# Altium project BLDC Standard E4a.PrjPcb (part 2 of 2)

## Sheet BLDC Standard sheet 4.SchDoc
size 431 x 279 mm; Date: Not shown in title block; ApprovedBy: Not shown in title block; CheckedBy: Not shown in title block; Author: Not shown in title block; CompanyName: Not shown in title block; Engineer: Not shown in title block; Organization: Not shown in title block; Address1: Not shown in title block; Address2: Not shown in title block; Address3: Not shown in title block; Address4: Not shown in title block; DocumentNumber: 1; Revision: Use project parameter SCH_Rev; SheetNumber: 4; SheetTotal: 4; PageSetup: Record=PageOptions|CenterHorizontal=True|CenterVertical=True|PrintScale=0.96|XCorrection=1.00|YCorrection=1.00|PrintKind=0|BorderSize=5000000|LeftOffset=0|BottomOffset=0|Orientation=2|PaperLength=1000|PaperWidth=1000|Scale=100|PaperSource=15|PrintQuality=600|MediaType=1|DitherType=10|PaperKind=11x17|PrintScaleMode=1
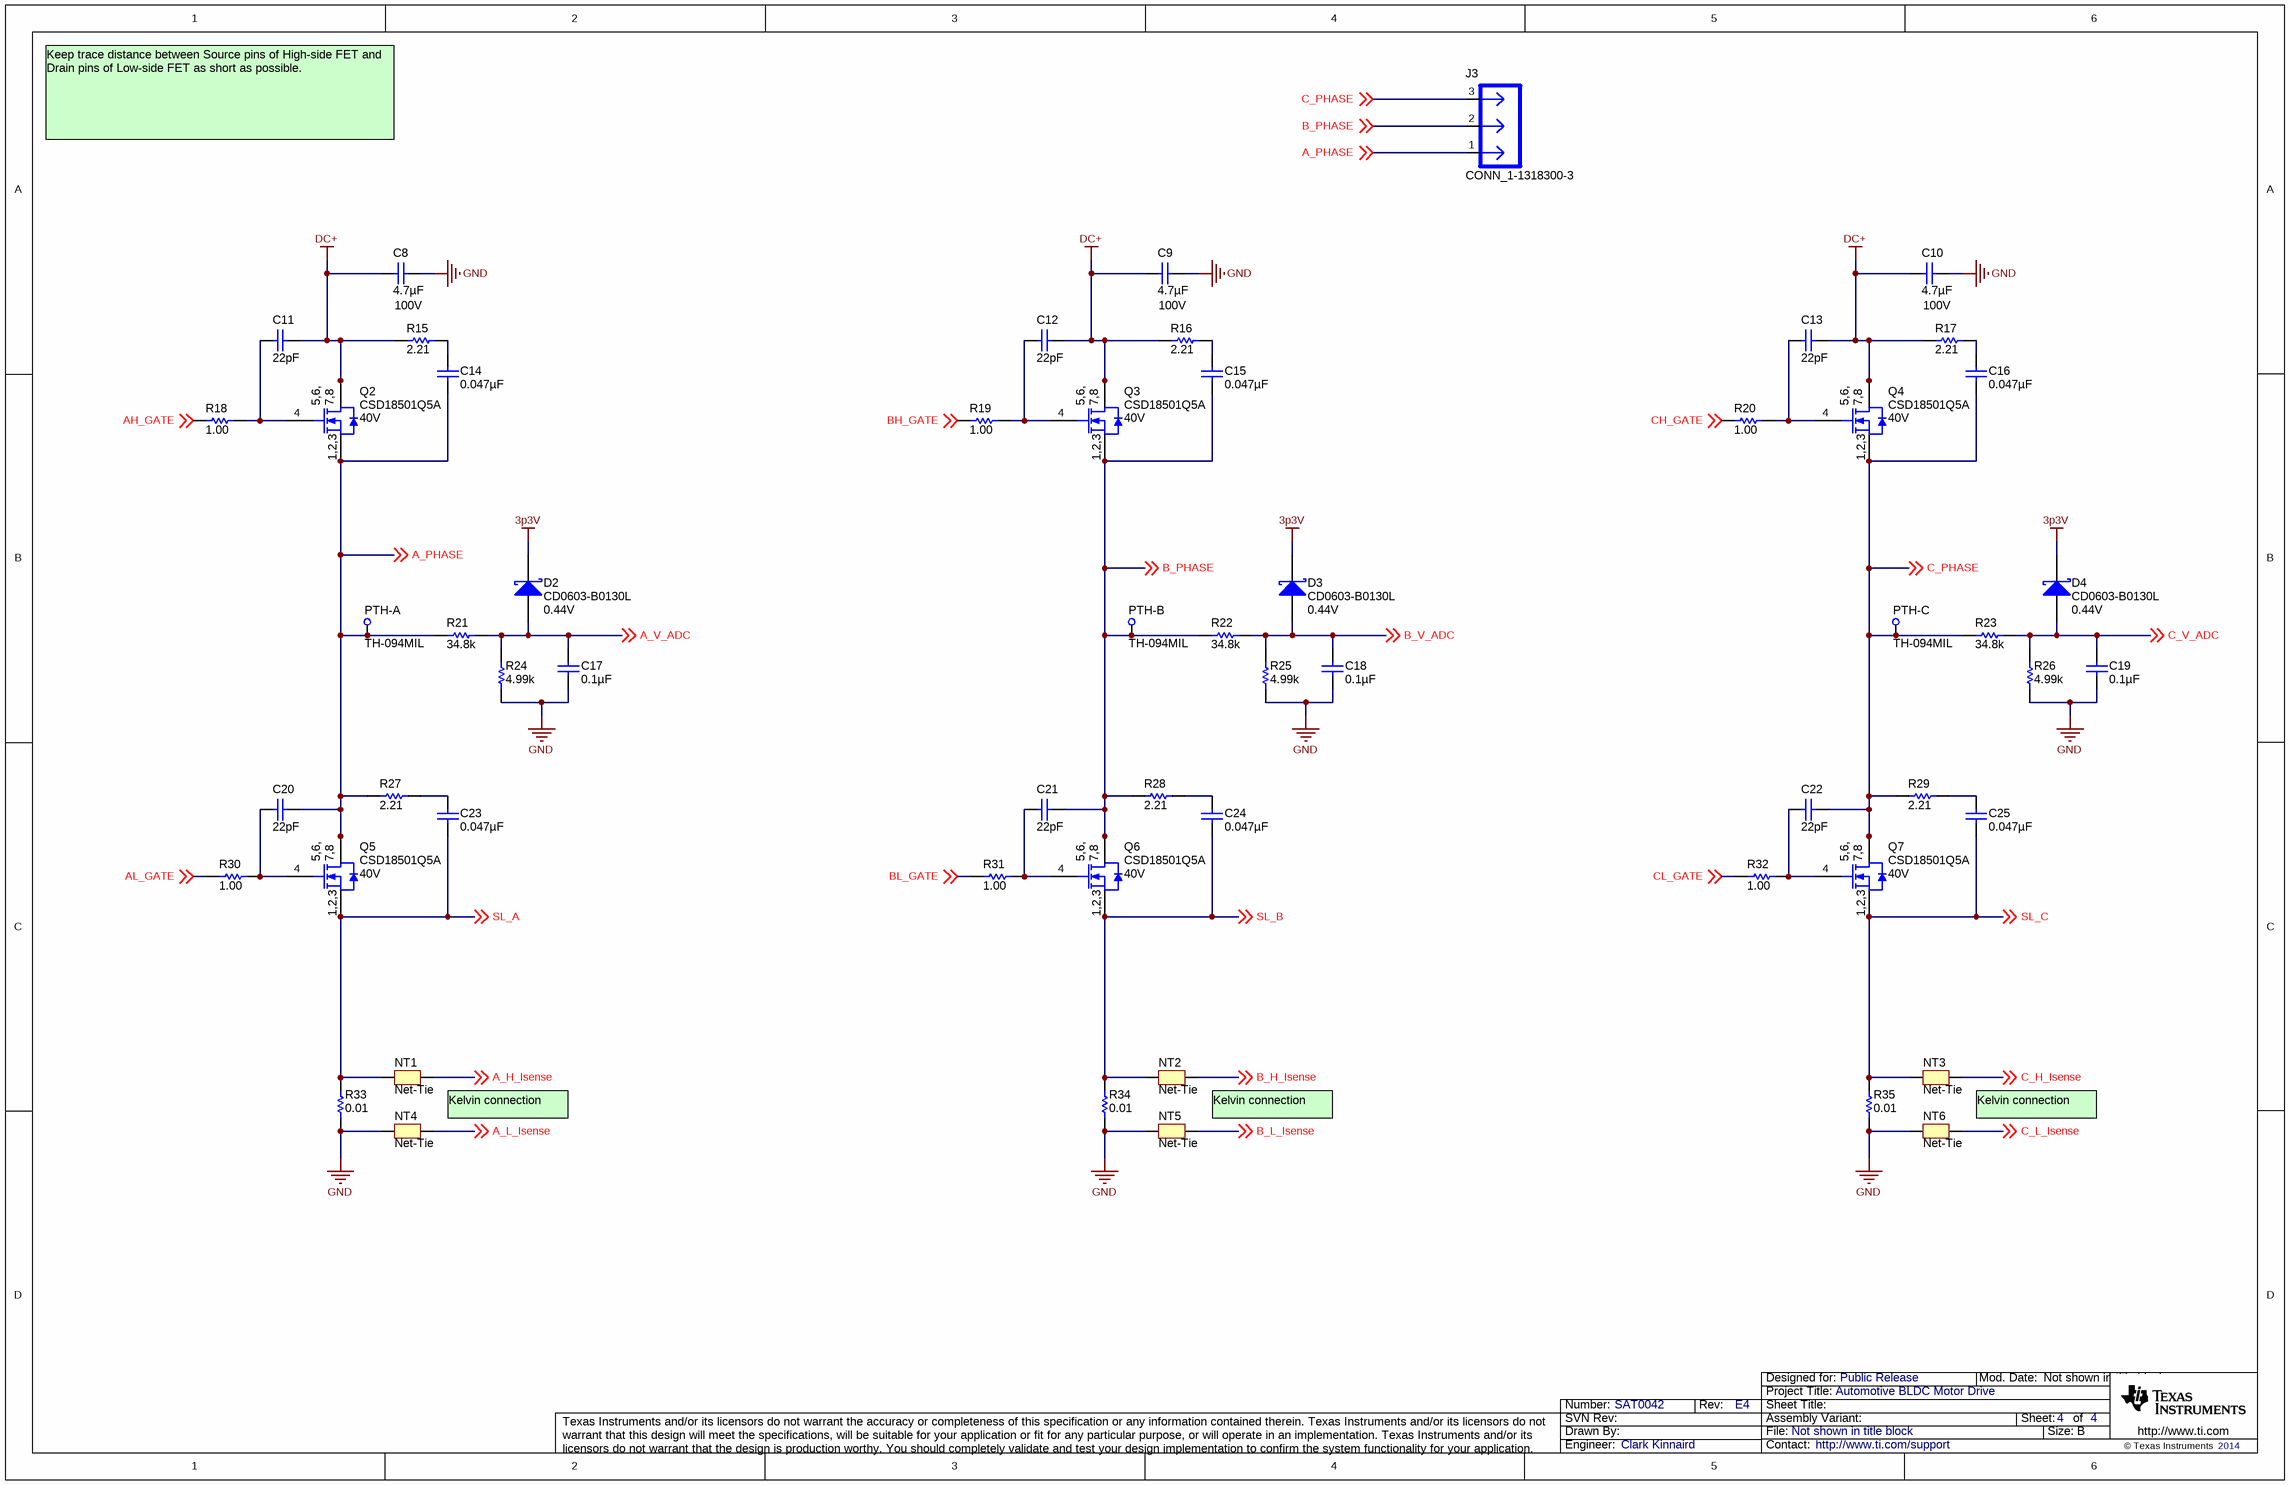
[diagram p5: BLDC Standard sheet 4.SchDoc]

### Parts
C8  ValueDisplayed: 4.7µF  Value2: 100V  [2220]  (hidden comment: C5750X7R2A475M)
C9  ValueDisplayed: 4.7µF  Value2: 100V  [2220]  (hidden comment: C5750X7R2A475M)
C10  ValueDisplayed: 4.7µF  Value2: 100V  [2220]  (hidden comment: C5750X7R2A475M)
C11  ValueDisplayed: 22pF  [0603]  (hidden comment: 06035A220JAT2A)
C12  ValueDisplayed: 22pF  [0603]  (hidden comment: 06035A220JAT2A)
C13  ValueDisplayed: 22pF  [0603]  (hidden comment: 06035A220JAT2A)
C14  ValueDisplayed: 0.047µF  [0603]  (hidden comment: C1608X7R1H473K)
C15  ValueDisplayed: 0.047µF  [0603]  (hidden comment: C1608X7R1H473K)
C16  ValueDisplayed: 0.047µF  [0603]  (hidden comment: C1608X7R1H473K)
C17  ValueDisplayed: 0.1µF  [0805_HV]  (hidden comment: C0805C104K4RACTU)
C18  ValueDisplayed: 0.1µF  [0805_HV]  (hidden comment: C0805C104K4RACTU)
C19  ValueDisplayed: 0.1µF  [0805_HV]  (hidden comment: C0805C104K4RACTU)
C20  ValueDisplayed: 22pF  [0603]  (hidden comment: 06035A220JAT2A)
C21  ValueDisplayed: 22pF  [0603]  (hidden comment: 06035A220JAT2A)
C22  ValueDisplayed: 22pF  [0603]  (hidden comment: 06035A220JAT2A)
C23  ValueDisplayed: 0.047µF  [0603]  (hidden comment: C1608X7R1H473K)
C24  ValueDisplayed: 0.047µF  [0603]  (hidden comment: C1608X7R1H473K)
C25  ValueDisplayed: 0.047µF  [0603]  (hidden comment: C1608X7R1H473K)
D2  CD0603-B0130L  value 0.44V  [Diode_0603]
D3  CD0603-B0130L  value 0.44V  [Diode_0603]
D4  CD0603-B0130L  value 0.44V  [Diode_0603]
J3  CONN_1-1318300-3  [CONN_1-1318300-3]
NT1  Net-Tie  [Net-Tie_10mil]  (net tie, no BOM)
NT2  Net-Tie  [Net-Tie_10mil]  (net tie, no BOM)
NT3  Net-Tie  [Net-Tie_10mil]  (net tie, no BOM)
NT4  Net-Tie  [Net-Tie_10mil]  (net tie, no BOM)
NT5  Net-Tie  [Net-Tie_10mil]  (net tie, no BOM)
NT6  Net-Tie  [Net-Tie_10mil]  (net tie, no BOM)
PTH-A  TH-094MIL  [TH-094MIL]
PTH-B  TH-094MIL  [TH-094MIL]
PTH-C  TH-094MIL  [TH-094MIL]
Q2  CSD18501Q5A  value 40V  [TRANS_NexFET_Q5A]
Q3  CSD18501Q5A  value 40V  [TRANS_NexFET_Q5A]
Q4  CSD18501Q5A  value 40V  [TRANS_NexFET_Q5A]
Q5  CSD18501Q5A  value 40V  [TRANS_NexFET_Q5A]
Q6  CSD18501Q5A  value 40V  [TRANS_NexFET_Q5A]
Q7  CSD18501Q5A  value 40V  [TRANS_NexFET_Q5A]
R15  value 2.21  [0603]  (hidden comment: CRCW06032R21FKEA)
R16  value 2.21  [0603]  (hidden comment: CRCW06032R21FKEA)
R17  value 2.21  [0603]  (hidden comment: CRCW06032R21FKEA)
R18  value 1.00  [0402]  (hidden comment: CRCW04021R00FKED)
R19  value 1.00  [0402]  (hidden comment: CRCW04021R00FKED)
R20  value 1.00  [0402]  (hidden comment: CRCW04021R00FKED)
R21  value 34.8k  [0603]  (hidden comment: CRCW060334K8FKEA)
R22  value 34.8k  [0603]  (hidden comment: CRCW060334K8FKEA)
R23  value 34.8k  [0603]  (hidden comment: CRCW060334K8FKEA)
R24  value 4.99k  [0603]  (hidden comment: CRCW06034K99FKEA)
R25  value 4.99k  [0603]  (hidden comment: CRCW06034K99FKEA)
R26  value 4.99k  [0603]  (hidden comment: CRCW06034K99FKEA)
R27  value 2.21  [0603]  (hidden comment: CRCW06032R21FKEA)
R28  value 2.21  [0603]  (hidden comment: CRCW06032R21FKEA)
R29  value 2.21  [0603]  (hidden comment: CRCW06032R21FKEA)
R30  value 1.00  [0402]  (hidden comment: CRCW04021R00FKED)
R31  value 1.00  [0402]  (hidden comment: CRCW04021R00FKED)
R32  value 1.00  [0402]  (hidden comment: CRCW04021R00FKED)
R33  value 0.01  [2512_WIDE]  (hidden comment: FCSL64R010FER)
R34  value 0.01  [2512_WIDE]  (hidden comment: FCSL64R010FER)
R35  value 0.01  [2512_WIDE]  (hidden comment: FCSL64R010FER)

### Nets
3p3V: D2.1(K) D3.1(K) D4.1(K)
DC+: C8.1 C9.1 C10.1 C11.1 C12.1 C13.1 Q2.5(D) Q2.6(D) Q2.7(D) Q2.8(D) Q2.9(D) Q3.5(D) Q3.6(D) Q3.7(D) Q3.8(D) Q3.9(D) Q4.5(D) Q4.6(D) Q4.7(D) Q4.8(D) Q4.9(D) R15.1 R16.1 R17.1
GND: C8.2 C9.2 C10.2 C17.2 C18.2 C19.2 NT4.1 NT5.1 NT6.1 R24.1 R25.1 R26.1 R33.1 R34.1 R35.1
A_H_Isense: NT1.2 ; off-sheet A_H_Isense
A_L_Isense: NT4.2 ; off-sheet A_L_Isense
A_PHASE: C14.2 C20.1 J3.1 PTH-A.1 Q2.1(S) Q2.2(S) Q2.3(S) Q5.5(D) Q5.6(D) Q5.7(D) Q5.8(D) Q5.9(D) R21.1 R27.1 ; off-sheet A_PHASE
A_V_ADC: C17.1 D2.2(A) R21.2 R24.2 ; off-sheet A_V_ADC
AH_GATE: R18.1 ; off-sheet AH_GATE
AL_GATE: R30.1 ; off-sheet AL_GATE
B_H_Isense: NT2.2 ; off-sheet B_H_Isense
B_L_Isense: NT5.2 ; off-sheet B_L_Isense
B_PHASE: C15.2 C21.1 J3.2 PTH-B.1 Q3.1(S) Q3.2(S) Q3.3(S) Q6.5(D) Q6.6(D) Q6.7(D) Q6.8(D) Q6.9(D) R22.1 R28.1 ; off-sheet B_PHASE
B_V_ADC: C18.1 D3.2(A) R22.2 R25.2 ; off-sheet B_V_ADC
BH_GATE: R19.1 ; off-sheet BH_GATE
BL_GATE: R31.1 ; off-sheet BL_GATE
C_H_Isense: NT3.2 ; off-sheet C_H_Isense
C_L_Isense: NT6.2 ; off-sheet C_L_Isense
C_PHASE: C16.2 C22.1 J3.3 PTH-C.1 Q4.1(S) Q4.2(S) Q4.3(S) Q7.5(D) Q7.6(D) Q7.7(D) Q7.8(D) Q7.9(D) R23.1 R29.1 ; off-sheet C_PHASE
C_V_ADC: C19.1 D4.2(A) R23.2 R26.2 ; off-sheet C_V_ADC
CH_GATE: R20.1 ; off-sheet CH_GATE
CL_GATE: R32.1 ; off-sheet CL_GATE
SL_A: C23.2 NT1.1 Q5.1(S) Q5.2(S) Q5.3(S) R33.2 ; off-sheet SL_A
SL_B: C24.2 NT2.1 Q6.1(S) Q6.2(S) Q6.3(S) R34.2 ; off-sheet SL_B
SL_C: C25.2 NT3.1 Q7.1(S) Q7.2(S) Q7.3(S) R35.2 ; off-sheet SL_C
NetC11_2: C11.2 Q2.4(G) R18.2
NetC12_2: C12.2 Q3.4(G) R19.2
NetC13_2: C13.2 Q4.4(G) R20.2
NetC14_1: C14.1 R15.2
NetC15_1: C15.1 R16.2
NetC16_1: C16.1 R17.2
NetC20_2: C20.2 Q5.4(G) R30.2
NetC21_2: C21.2 Q6.4(G) R31.2
NetC22_2: C22.2 Q7.4(G) R32.2
NetC23_1: C23.1 R27.2
NetC24_1: C24.1 R28.2
NetC25_1: C25.1 R29.2

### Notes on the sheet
- Keep trace distance between Source pins of High-side FET and Drain pins of Low-side FET as short as possible.
- Kelvin connection

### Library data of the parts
C8-C10 = C5750X7R2A475M: CAP, CERM, 4.7uF, 100V, +/-20%, X7R, 2220; Manufacturer: TDK; Polarized: N; CompType: Capacitor; U/M: EA; Cap_F: 0.0000047; Tolerance_%: 20; ESR_Ohm: 0.0015; Value1: 0.0015 ohm; VDC_V: 100; IRMS_A: 5.5; TaMin_C: -55; TaMax_C: 125
C11-C13 C20-C22 = 06035A220JAT2A: CAP, CERM, 22pF, 50V, +/-5%, C0G/NP0, 0603; Manufacturer: AVX; Polarized: N; CompType: Capacitor; U/M: EA; Cap_F: 0.000000000022; Tolerance_%: 5; ESR_Ohm: 0.259; Value1: 0.259 ohm; VDC_V: 50; TaMin_C: -55; TaMax_C: 125
C14-C16 C23-C25 = C1608X7R1H473K: CAP, CERM, 0.047uF, 50V, +/-10%, X7R, 0603; Manufacturer: TDK; Polarized: N; CompType: Capacitor; U/M: EA; Cap_F: 0.000000047; Tolerance_%: 10; ESR_Ohm: 0.0234; Value1: 0.0234 ohm; VDC_V: 50; TaMin_C: -55; TaMax_C: 125
C17-C19 = C0805C104K4RACTU: CAP, CERM, 0.1uF, 16V, +/-10%, X7R, 0805; Manufacturer: Kemet; Polarized: N; CompType: Capacitor; U/M: EA; Cap_F: 0.0000001; Tolerance_%: 10; ESR_Ohm: 0.064; Value1: 0.064 ohm; VDC_V: 16; IRMS_A: 1.64; TaMin_C: -55; TaMax_C: 125; Cap_Case: 0805
D2-D4 = CD0603-B0130L: Diode, Schottky, 35V, 0.1A, 0603 Diode; Manufacturer: Bourns; U/M: EA; Vf_V: 0.44; Io_A: 0.1; Vr_V: 35; TJmax_C: 125
J3 = CONN_1-1318300-3: Connector, Vertical, 0.156 mil; Manufacturer: Tyco; Area: 185000
NT1-NT6 = Net-Tie: Single point connection between nets.; SymbolCreator: codlsc
PTH-A PTH-B PTH-C = TH-094MIL: Plated Through Hole, Dia. 0.094; Manufacturer: Mill-Max; PartNumber: 3233-x-0x-xx-00-00-0x-0; area: 32.400; Value: 3233-x-0x-xx-00-00-0x-0
Q2-Q7 = CSD18501Q5A: MOSFET, N-CH, 40V, 22A, SON 5x6mm; Manufacturer: Texas Instruments; Alternate Manufacturer: None; U/M: EA; ChType: N; VdsMax_V: 40; Value1: 0.0043 ohm; Rdson45_Ohm: 0.0043; Value2: 20 nC; QgTyp_nC: 20; IdsMax_A: 22
R15-R17 R27-R29 = CRCW06032R21FKEA: RES, 2.21 ohm, 1%, 0.1W, 0603; Manufacturer: Vishay-Dale; CompType: Resistor; Value_Code: 2R21; Tolerance_%: 1; Power_W: 0.1; VDC_V: 75; TempCo: 100 ppm/C; EIA_Code: E96; U/M: EA
R18-R20 R30-R32 = CRCW04021R00FKED: RES, 1.00 ohm, 1%, 0.063W, 0402; Manufacturer: Vishay-Dale; CompType: Resistor; Res_ohm: 1; Value_Code: 1R00; Power_W: 0.063; VDC_V: 50; TempCo: 100 ppm/C; EIA_Code: E96; U/M: EA
R21-R23 = CRCW060334K8FKEA: RES, 34.8k ohm, 1%, 0.1W, 0603; Manufacturer: Vishay-Dale; CompType: Resistor; Res_ohm: 34800; Value_Code: 34k8; Tolerance_%: 1; Power_W: 0.1; VDC_V: 75; TempCo: 100 ppm/C; EIA_Code: E96; U/M: EA
R24-R26 = CRCW06034K99FKEA: RES, 4.99k ohm, 1%, 0.1W, 0603; Manufacturer: Vishay-Dale; CompType: Resistor; Res_ohm: 4990; Value_Code: 4k99; Tolerance_%: 1; Power_W: 0.1; VDC_V: 75; TempCo: 100 ppm/C; EIA_Code: E96; U/M: EA
R33-R35 = FCSL64R010FER: RES, 0.01 ohm, 1%, 2W, 2512 WIDE; Manufacturer: Ohmite; CompType: Resistor; Value_Code: R010; Tolerance_%: 1; Power_W: 2; TempCo: 75 ppm/C; EIA_Code: E96; U/M: EA

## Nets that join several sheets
3p3V: BLDC Standard sheet 1 (R2.2 R12.2), BLDC Standard sheet 2 (15 pins), BLDC Standard sheet 3 (11 pins), BLDC Standard sheet 4 (D2.1 D3.1 D4.1)
DC+: BLDC Standard sheet 1 (9 pins), BLDC Standard sheet 2 (R37.2 R39.1), BLDC Standard sheet 3 (8 pins), BLDC Standard sheet 4 (24 pins)
GND: BLDC Standard sheet 1 (17 pins), BLDC Standard sheet 2 (26 pins), BLDC Standard sheet 3 (32 pins), BLDC Standard sheet 4 (15 pins)
A_H_Isense: BLDC Standard sheet 3 (C64.1 U6.33), BLDC Standard sheet 4 (NT1.2)
A_I_ADC: BLDC Standard sheet 2 (TP10.1 U3.8 U3.15), BLDC Standard sheet 3 (C60.1 R63.2)
A_L_Isense: BLDC Standard sheet 3 (C64.2 U6.32), BLDC Standard sheet 4 (NT4.2)
A_PHASE: BLDC Standard sheet 3 (C47.2 U6.46), BLDC Standard sheet 4 (14 pins)
A_V_ADC: BLDC Standard sheet 2 (TP9.1 U3.18), BLDC Standard sheet 4 (C17.1 D2.2 R21.2 R24.2)
ADC_REF: BLDC Standard sheet 2 (5 pins), BLDC Standard sheet 3 (C54.1 R65.2 U6.24)
AH_GATE: BLDC Standard sheet 3 (U6.47), BLDC Standard sheet 4 (R18.1)
AH_PWM: BLDC Standard sheet 2 (U3.29), BLDC Standard sheet 3 (U6.17)
AL_GATE: BLDC Standard sheet 3 (U6.45), BLDC Standard sheet 4 (R30.1)
AL_PWM: BLDC Standard sheet 2 (U3.28), BLDC Standard sheet 3 (U6.18)
B_H_Isense: BLDC Standard sheet 3 (C65.1 U6.31), BLDC Standard sheet 4 (NT2.2)
B_I_ADC: BLDC Standard sheet 2 (TP8.1 U3.13 U3.17), BLDC Standard sheet 3 (C59.1 R62.2)
B_L_Isense: BLDC Standard sheet 3 (C65.2 U6.30), BLDC Standard sheet 4 (NT5.2)
B_PHASE: BLDC Standard sheet 3 (C49.2 U6.41), BLDC Standard sheet 4 (14 pins)
B_V_ADC: BLDC Standard sheet 2 (TP7.1 U3.6), BLDC Standard sheet 4 (C18.1 D3.2 R22.2 R25.2)
BH_GATE: BLDC Standard sheet 3 (U6.42), BLDC Standard sheet 4 (R19.1)
BH_PWM: BLDC Standard sheet 2 (U3.37), BLDC Standard sheet 3 (U6.19)
BL_GATE: BLDC Standard sheet 3 (U6.40), BLDC Standard sheet 4 (R31.1)
BL_PWM: BLDC Standard sheet 2 (U3.38), BLDC Standard sheet 3 (U6.20)
C_H_Isense: BLDC Standard sheet 3 (C66.2 R70.1), BLDC Standard sheet 4 (NT3.2)
C_I_ADC: BLDC Standard sheet 2 (TP12.1 U3.4 U3.7), BLDC Standard sheet 3 (C62.1 R64.2)
C_L_Isense: BLDC Standard sheet 3 (C66.1 R69.1), BLDC Standard sheet 4 (NT6.2)
C_PHASE: BLDC Standard sheet 3 (C51.2 U6.36), BLDC Standard sheet 4 (14 pins)
C_V_ADC: BLDC Standard sheet 2 (TP11.1 U3.16), BLDC Standard sheet 4 (C19.1 D4.2 R23.2 R26.2)
CH_GATE: BLDC Standard sheet 3 (U6.37), BLDC Standard sheet 4 (R20.1)
CH_PWM: BLDC Standard sheet 2 (U3.39), BLDC Standard sheet 3 (U6.21)
CL_GATE: BLDC Standard sheet 3 (U6.35), BLDC Standard sheet 4 (R32.1)
CL_PWM: BLDC Standard sheet 2 (U3.40), BLDC Standard sheet 3 (U6.22)
EN_GATE: BLDC Standard sheet 2 (U3.31), BLDC Standard sheet 3 (R61.2 U6.16)
FAULT: BLDC Standard sheet 2 (U3.48), BLDC Standard sheet 3 (R54.2 U6.6)
IN_PWM: BLDC Standard sheet 1 (R2.1 R3.2 U8.1), BLDC Standard sheet 2 (U3.1)
nSCS: BLDC Standard sheet 2 (U3.25), BLDC Standard sheet 3 (U6.8)
OCTW: BLDC Standard sheet 2 (U3.36), BLDC Standard sheet 3 (R52.2 U6.5)
OUT_PWM: BLDC Standard sheet 1 (R14.1 U8.5), BLDC Standard sheet 2 (U3.41)
PWRGD: BLDC Standard sheet 2 (U3.19), BLDC Standard sheet 3 (D6.1 R58.1 U6.4)
SCLK: BLDC Standard sheet 2 (U3.24), BLDC Standard sheet 3 (R59.2 U6.11)
SDI: BLDC Standard sheet 2 (U3.27), BLDC Standard sheet 3 (U6.9)
SDO: BLDC Standard sheet 2 (U3.26), BLDC Standard sheet 3 (U6.10)
SL_A: BLDC Standard sheet 3 (U6.44), BLDC Standard sheet 4 (6 pins)
SL_B: BLDC Standard sheet 3 (U6.39), BLDC Standard sheet 4 (6 pins)
SL_C: BLDC Standard sheet 3 (U6.34), BLDC Standard sheet 4 (6 pins)

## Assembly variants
001: not fitted L3 R3 R14 R36 R71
